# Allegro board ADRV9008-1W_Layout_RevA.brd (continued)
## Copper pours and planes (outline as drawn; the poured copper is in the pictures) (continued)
VDDA_3P3 on BOTTOM: 107.32,22.27 108.85,20.75 108.85,19.35 108.56,19.06 101.31,19.06 101.23,19.14 101.23,20.36 101.28,20.41 101.71,20.41 101.99,20.68 101.99,23.29 102.75,24.05 104.28,24.05 106.05,22.27
VDDA_3P3 on L3_PWR: 33.78,39.41 33.78,40.68 37.47,44.36 43.69,44.36 44.83,45.51 44.83,57.19 45.6,57.95 45.85,57.95 46.48,57.32 46.48,48.05 47.37,47.16 86.62,47.16 105.04,28.75 105.04,20.49 103.39,18.84 99.45,18.84 97.93,20.37 60.21,20.37 56.31,24.27 56.31,37.42 52.8,40.93 36.58,40.93 35.05,39.41
VDDA_3P3 on L10_SIG: 71.04,7.63 76.08,2.59 93.86,2.59 102.32,11.05 102.32,12.57 105.55,15.79 105.55,20.87 104.15,22.27 102.63,22.27 101.99,21.64 101.99,21.13 101.23,20.37 97.29,20.37 92.46,15.53 67.06,15.53 65.66,14.14 64.01,14.14 63.25,13.37 61.6,13.37 57.03,8.81 57.03,8.29 58.29,7.03 67.19,7.03 67.81,7.65
1P3_BUCK_OUT on BOTTOM: 80.07,8.67 80.07,5.3 79.92,5.14 71.54,5.14 71.46,5.22 71.46,8.65 71.59,8.78 79.97,8.78
3P3V_CLK1 on BOTTOM: 109.48,17.95 109.48,20.62 109.61,20.75 111.25,20.75 112.09,19.91 112.09,18.14 111.64,17.7 109.74,17.7
3P3V_CLK1 on L3_PWR: 146.34,19.16 128.41,19.16 125.87,21.7 121.87,21.7 119.96,19.8 114.12,19.8 112.28,17.95 109.74,17.95 109.1,18.59 109.1,26.84 111.64,29.38 137.52,29.38 140.79,32.66 140.79,49.42 138.99,51.22 88.39,51.22 82.81,56.81 82.81,65.19 84.72,67.11 107.7,67.09 107.95,66.84 107.95,62.9 111.02,59.84 144.91,59.87 147.38,57.4 147.38,20.21
3P3V_CLK1 on L10_SIG: 81.92,54.49 82.44,53.97 97.3,53.97 97.75,54.43 97.75,67.53 97.16,68.12 82.43,68.12 81.92,67.61
3P3V_VCXO on L3_PWR: 110.75,65.32 110.75,63.67 112.6,61.81 126.91,61.81 127.24,62.14 127.24,66.81 126.99,67.07 112.5,67.07
3P3VAUX on L12_PWR: 112.4,21.13 112.4,16.56 112.87,16.09 126.53,16.09 126.83,16.4 139.59,16.4 139.76,16.57 139.76,21.35 139.46,21.65 112.93,21.65
FMCA_VADJ on L12_PWR: 127.04,9.13 127.04,6.54 127.14,6.44 132.83,6.44 133.03,6.64 133.03,8.57 133.82,9.36 139.2,9.36 139.43,9.59 139.43,11.87 139.31,12 130.75,12 130.7,11.95 130.7,9.51 130.44,9.26 127.17,9.26
FMCA_VCC_3P3V on L12_PWR: 126.96,9.94 127.05,9.86 130.05,9.86 130.16,9.97 130.16,12.33 130.57,12.74 139.26,12.74 139.84,12.15 139.84,9.21 139.94,9.11 142.68,9.11 142.79,9.21 142.79,15.48 142.58,15.68 127.04,15.68 126.96,15.61
FMCA_VCC_12P0V on TOP: 120.67,9.69 130.18,9.69 132.07,11.58 132.07,12.22 132.49,12.64 142.48,12.64 142.61,12.76 142.61,16.55 142.43,16.73 140.86,16.73 140.75,16.62 140.75,15.95 140.34,15.54 130.31,15.54 129.17,14.4 124.98,14.4 123.83,15.54 117.74,15.54 117.48,15.29 117.48,12.87
INPUT_VOLTAGE on TOP: 125.61,6.65 117.55,6.65 117.17,6.27 117.17,4.11 117.55,3.73 125.61,3.73 125.93,4.05 125.93,6.33
INPUT_VOLTAGE on BOTTOM: 85.86,6.62 85.76,6.52 83.93,6.52 83.83,6.62 83.83,8.8 84.98,9.94 86.02,9.94 86.07,9.89 86.07,8.93 85.86,8.72
INPUT_VOLTAGE on BOTTOM: 85.71,16.27 84.95,16.27 84.87,16.19 84.87,15.84 84.82,15.79 83.5,15.79 83.45,15.84 83.05,15.84 82.87,16.01 82.87,20.08 82.89,20.1 84.65,20.1 84.7,20.05 84.7,18.3 85.76,17.23 85.76,16.32
INPUT_VOLTAGE on BOTTOM: 100.77,14.67 100.77,10.43 100.67,10.33 98.54,10.33 98.42,10.44 98.42,14.73 98.49,14.8 100.65,14.8
INPUT_VOLTAGE on L12_PWR: 102.24,14.65 117.61,14.65 125.93,6.33 125.93,4.05 125.1,3.22 106.68,3.22 103.89,6.02 84.69,6.02 82.89,7.81 82.89,18.29 85.29,20.68 96.21,20.68
UNNAMED_4_CAP_I274_N1 on BOTTOM: 107.59,60.77 107.59,59.22 107.49,59.12 105.89,59.12 105.84,59.17 105.84,60.77 105.89,60.82 107.54,60.82
UNNAMED_5_CNTP1P_I268_N1 on BOTTOM: 24.01,62.02 21.47,62.02 21.34,62.14 21.34,64.68 21.59,64.94 24.13,64.94 24.39,64.68 24.39,63.41 24.13,63.16 24.13,62.14
UNNAMED_11_ADP5054_I29_SW11 on BOTTOM: 84.9,15.43 84.9,14.54 84.85,14.49 83.32,14.49 81.83,12.99 81.29,12.99 80.78,12.48 80.78,11.98 80.66,11.85 79.95,11.85 79.82,11.98 79.44,11.98 79.39,12.03 79.39,12.94 80.38,13.93 80.38,17.69 80.45,17.77 82.16,17.77 82.26,17.67 82.26,15.74 82.41,15.58 83.86,15.58 83.99,15.46 84.87,15.46
UNNAMED_11_ADP5054_I29_SW21 on BOTTOM: 84.06,10.25 82.99,9.18 82.99,5.09 82.94,5.04 80.66,5.04 80.58,5.12 80.58,10.48 80.28,10.78 80.28,11.34 80.3,11.37 81.01,11.37 81.37,11.01 82.77,11.01 83.05,11.29 84.85,11.29 84.9,11.24 84.9,10.58 84.57,10.25
UNNAMED_11_ADP5054_I29_SW31 on BOTTOM: 97.85,13.07 92.7,13.07 92.57,13.2 92.57,14.59 92.62,14.64 97.85,14.64 97.9,14.59 97.9,13.12
UNNAMED_11_ADP5054_I29_SW41 on BOTTOM: 93.71,10.78 92.54,10.78 92.49,10.83 92.49,12.33 92.72,12.56 97.83,12.56 97.88,12.51 97.88,10.58 97.8,10.5 93.99,10.5
UNNAMED_11_CAP_I54_N2 on BOTTOM: 94.09,8.19 94.09,9.69 94.17,9.77 101.41,9.77 101.64,9.99 104.97,9.99 105.15,9.81 105.16,8.67 105.54,8.29 106.81,8.29 107.06,8.04 107.06,7.28 106.94,7.15 105.16,7.15 104.37,6.36 96.35,6.36 96.3,6.41 96.3,8.06 96.23,8.14 94.15,8.14
UNNAMED_11_CAP_I55_N2 on BOTTOM: 94.09,16.88 94.09,15.38 94.17,15.3 101.41,15.3 101.64,15.07 107.07,15.07 107.07,16.35 104.91,18.5 100.75,18.5 100.55,18.71 96.35,18.71 96.3,18.66 96.3,17.01 96.23,16.93 94.15,16.93
UNNAMED_11_CAP_I59_N2 on BOTTOM: 79.82,17.56 79.82,14.19 79.67,14.03 70.73,14.03 70.65,14.11 70.65,15.3 71.01,15.66 71.01,17.01 71.11,17.11 72.76,17.11 73.32,17.67 79.72,17.67
UNNAMED_11_CN2P_I1_N1 on TOP: 111.83,15.35 111.83,11.86 113.04,10.65 113.04,8.49 112.34,7.79 109.99,7.79 109.36,8.43 109.36,15.29 109.61,15.54 111.64,15.54
UNNAMED_11_DIO_I7_P on TOP: 113.42,15.54 113.23,15.35 113.23,11.29 114.06,10.46 114.06,8.56 114.82,7.79 122.31,7.8 122.82,8.3 122.82,10.33 122.31,10.84 118.75,10.84 116.47,13.13 116.47,15.29 116.21,15.54

Small or netless copper shapes (teardrops, artwork), in the pictures only: 2 on TOP, 3 on BOTTOM

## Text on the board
Ref Des/Silkscreen Bottom: LO_I/O | RX1 | RX2
Ref Des/Silkscreen Top: VDDA1P3_ | AUX_VCO_LDO | RF_VCO_LDO | VDDA1P3_RX | VDDA1P3_RX_RF | GND | ANLG | POWER_OK | VOUT3_3V3 | REF_CLK_IN | 6.0-12.0V DC | 2A MAX | STATUS1 | STATUS2 | FMCA_VCC_12P0V | SYNCINB0- | SYNCINB0+ | FMCA_VCC_3P3V | VDDA1P8_BB | VDDA1P3_BB | CLOCK_SYNTH | GPIO_3P3 | VCO_LDO | VDDA1P3_CLK_ | 10 | 11 | VDDA1P3_SER | 8 | 9 | VDDA1P3_DES | 6 | 7 | 4 | 5 | N/C | RX1_EN | RX2_EN | 2 | 3 | VTUNE | RF_SYNTH_ | AUX_SYNTH_ | 0 | 1 | GPIO_1 | GPIO_18 | GPIO_15 | GPIO_14 | AUXADC3 | GPIO_12 | AUXADC2 | AUXADC1 | GPIO_10 | AUXADC0 | GPIO_8 | GPIO_9 | GPIO_7 | GPIO_6 | GPIO_0 | VDDA1P8_AN | SPI_DOUT_9528 | V_IN | SPI_DOUT | SYNCINB1+ | SPI_DOUT_DUT | SYNCINB1- | SPI_CLK | TEST | SPI_CSI | SPI_DIN | GP_INTERRUPT | FMCA_VADJ | RESETB | LO_I/0 | VDDA1P3_RF_LO | AUX_SYNTH | RF_SYNTH | RX1 | RX2 | POWER_IN | ADRV9008-1 W/PCBZ
DIMENSION: .087" | 30 DEGREES BOTH SIDES | SCORE DETAIL | SCORE EDGE | WEB .020 +/- .004
PAGE_OUTLINE: B | AS PER ECR-074509 | 19JAN18 | N.PARIKH | MARKET BOARD
User.15: CHARACTERISTIC IMPEDANCE = 100 OHMS +/- 10% DIFF PAIR | ARTWORK LINE WIDTH FOR | IMPEDANCE CONTROLLED LINES = 0.008"/0.006 AND 0.0036"/0.0064" | CHARACTERISTIC IMPEDANCE = 50 OHMS +/- 10% DIFF PAIR | IMPEDANCE CONTROLLED LINES = 0.032"/0.004" | ISOLA 370HR | ROGERS4003 | 50 OHMS 0.0045" SINGLE ENDED / 100 OHMS 0.0036"/0.0064" DIFF | 50 OHMS 0.0155" SINGLE ENDED; 0.032"/0.004" DIFF | 50 OHMS 0.0155" SINGLE ENDED / 100 OHMS 0.008"/0.006" DIFF | 100 OHMS 0.008"/0.006" DIFF | SEE NOTE 15
User.17: 08-      -07 | L2 GND
User.18: L3 PWR | 08-      -08
User.19: L4 GND | 08-      -09
User.20: 08-      -10 | L5 SIG
User.22: 08-      -11 | L6 GND
User.23: 08-      -12 | L7 SIG
User.24: 08-      -13 | L8 SIG
User.25: 08-      -14 | L9 GND
User.26: 08-      -15 | L10 SIG
User.27: L11 GND | 08-      -16
User.28: L12 PWR | 08-      -17
User.29: 08-      -18 | L13 GND
User.45: NOTES: | - MNC_LAYER: MUST-NOT-CUT-LAYER | - MAX_DEPTH: DEPTH FROM START LAYER TO THE | SURFACE OF MUST-NOT-CUT-LAYER | - MFG_STUB : MANUFACTURING STUB LENGTH | FIGURE | SIZE | 6.0 | 8.0 | 10.0 | 20.0 | 40.0 | 45.0 | 60.0 | 65.0 | 70.0 | 50.0 | 100.0 | 160.0 | 6.01 | 10.01 | 10.02 | PLATED | NON-PLATED | DRILL CHART: TOP to BOTTOM | ALL UNITS ARE IN MILS | DRILL CHART: TOP to L10_SIG | DRILL CHART: L11_GND to BOTTOM | QTY | 101 | 288 | 1052 | 103 | 43 | 69 | 5 | 2 | 8 | 109 | 106 | 14 | 136 | +3.0/-3.0 | +0.0/-0.0 | +2.0/-2.0 | TOLERANCE/NOTES | BD_SIZE | 18.0 | MNC_Layer | L5_SIG | L10_SIG | BACKDRILL: TOP to L4_GND | BACKDRILL: TOP to L9_GND | MAX_DEPTH | 26.22 | 50.38 | MFG_STUB | 3.0 | 6
